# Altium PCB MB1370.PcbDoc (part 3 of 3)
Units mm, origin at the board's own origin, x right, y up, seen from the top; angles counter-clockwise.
Board outline 166 x 117 mm, 4 copper layers (Top Layer, Signal Layer 1, Signal Layer 2, Bottom Layer), stack 1.614 mm thick; 79 components, 100 nets, 342 pads, 822 vias.
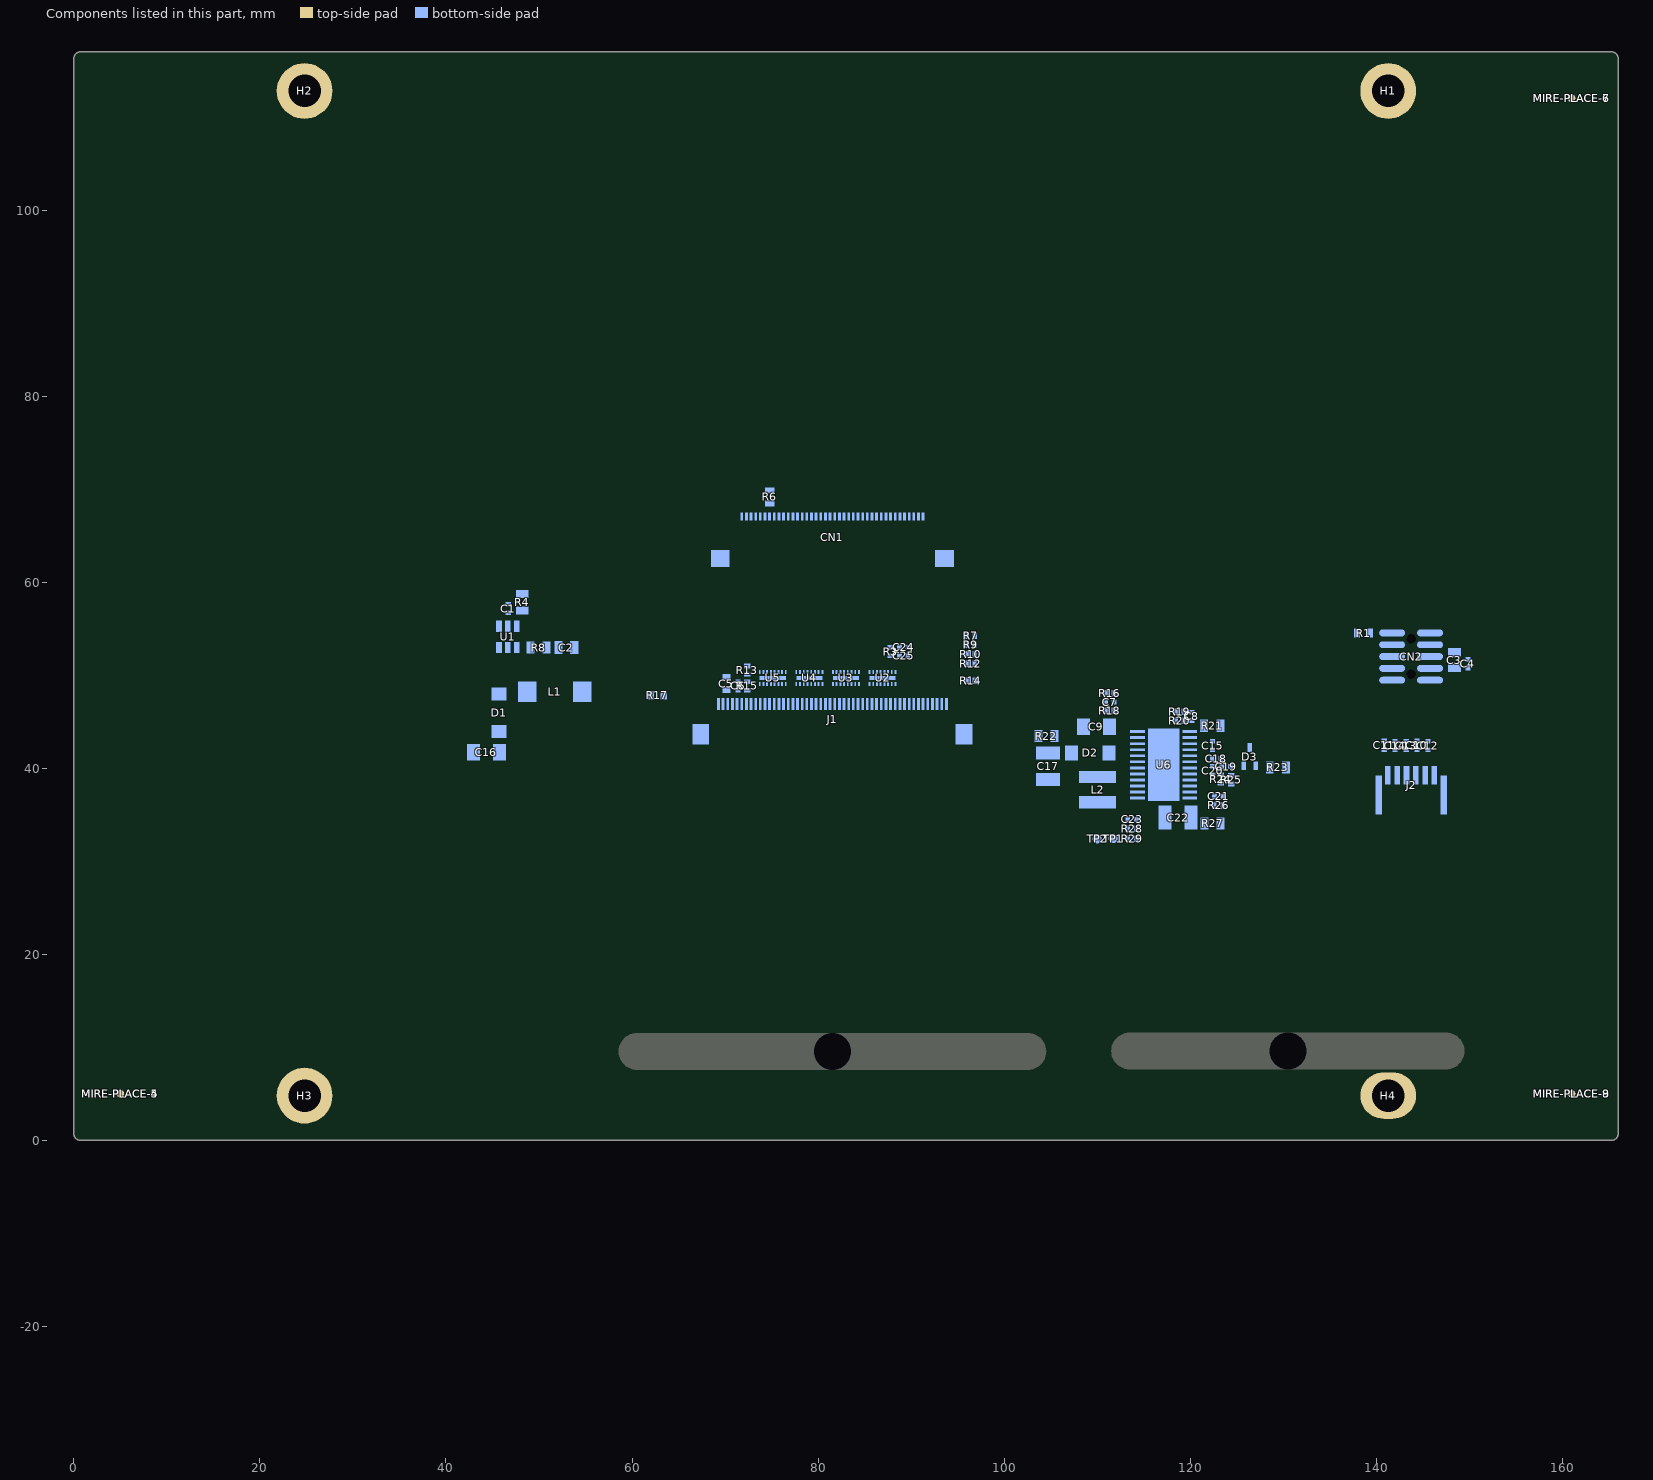
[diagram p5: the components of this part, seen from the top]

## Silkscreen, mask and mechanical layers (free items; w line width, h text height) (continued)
M21-Bottom Sheet Box:
  circle w0.254: c39.871,-31.223 r1.3
  region: 54.349,-32.316 65.105,-32.316 64.112,-29.823 56.254,-29.823 55.805,-29.064 53.597,-31.612
  region: 40.346,-23.986 55.873,-23.986 56.567,-25.762 57.778,-26.987 59.175,-25.127 59.175,-23.476 58.032,-22.079 56.596,-21.7 40.346,-21.7
  lines w0.254: 39.832,-21.7 40.594,-23.986 ; 40.086,-21.7 40.848,-23.986 ; 40.252,-21.698 41.014,-23.984 ; 40.34,-23.986 39.578,-21.7 56.342,-21.7 cw(c56.582,-24.341) 58.386,-26.285 55.32,-29.823 64.112,-29.823 ; 40.346,-23.986 44.038,-23.986 ; 42.983,-30.599 38.684,-19.821 58.134,-19.821 ; 42.984,-30.601 ccw(c45.534,-29.581) 45.782,-32.316 65.105,-32.316 60.759,-21.421 ; 44.038,-23.732 46.927,-32.112 ; 44.267,-23.741 47.136,-32.062 ; 44.521,-23.741 47.39,-32.062 ; 44.775,-23.741 47.644,-32.062 ; 45.029,-23.741 47.898,-32.062 ; 45.283,-23.741 48.152,-32.062 ; 45.537,-23.741 48.406,-32.062 ; 45.674,-23.986 58.667,-23.986 ; 45.791,-23.741 48.66,-32.062 ; 46.045,-23.741 48.914,-32.062 ; 46.172,-23.741 49.041,-32.062 ; 46.374,-23.732 49.263,-32.112 ; 52.698,-29.953 58.003,-23.831 ; 52.698,-29.572 58.003,-23.45 ; 52.825,-30.334 58.13,-24.212 ; 52.825,-30.08 58.13,-23.958 ; 52.825,-29.191 58.13,-23.069 ; 52.879,-30.525 58.13,-24.466 ; 52.897,-28.762 58.202,-22.641 ; 52.952,-30.715 58.257,-24.593 ; 53.079,-30.842 58.384,-24.72 ; 53.206,-30.969 58.511,-24.847 ; 53.333,-31.096 58.638,-24.974 ; 53.46,-31.477 58.765,-25.355 ; 53.46,-31.223 58.765,-25.101 ; 53.597,-31.612 59.019,-25.355 ; 54.607,-32.224 cw(c55.34,-29.675) 53.536,-27.731 55.901,-25.002 ccw(c55.571,-24.54) 55.545,-23.973 ; 56.228,-28.844 ccw(c56.526,-29.301) 56.631,-29.836 ; 58.135,-19.821 cw(c58.372,-22.424) 60.798,-21.453
  lines w0.3: 46.927,-32.112 49.263,-32.112 ; 66.688,-36.202 66.688,-16.202 ; 66.688,-31.202 126.688,-31.202 ; 66.688,-26.202 126.688,-26.202 ; 66.688,-21.202 126.688,-21.202 ; 86.688,-36.202 86.688,-21.202 ; 36.688,-36.202 126.688,-36.202 126.688,-16.202 36.688,-16.202 36.688,-36.202
  text "Project: '.Board_Name'" at 125.494,-19.418 h3
  text "Gerber:" at 85.505,-24.502 h3
  text "Layer:" at 125.494,-24.502 h3
  text "Ref: '.Board_Reference'" at 85.505,-29.502 h3
  text "Variant: '.VariantName'" at 125.494,-29.502 h3
  text "R" at 40.379,-31.985 h1.52
  text "Rev: '.Board_PCB_Revision'" at 85.562,-34.502 h3
  text "Date: '.Board_Document_Date'" at 125.494,-34.502 h3

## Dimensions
166,116.31 to -0.001,116.309 on M2-Board Dimensions
81.54,8.74 to 0.44,8.26 on M4-Bottom Dimensions
111.5,8.425 to 149.5,8.375 on M3-Top Dimensions
58.55,9.925 to 104.55,9.925 on M3-Top Dimensions
165.31,117 to 0.691,-0.001 on M2-Board Dimensions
